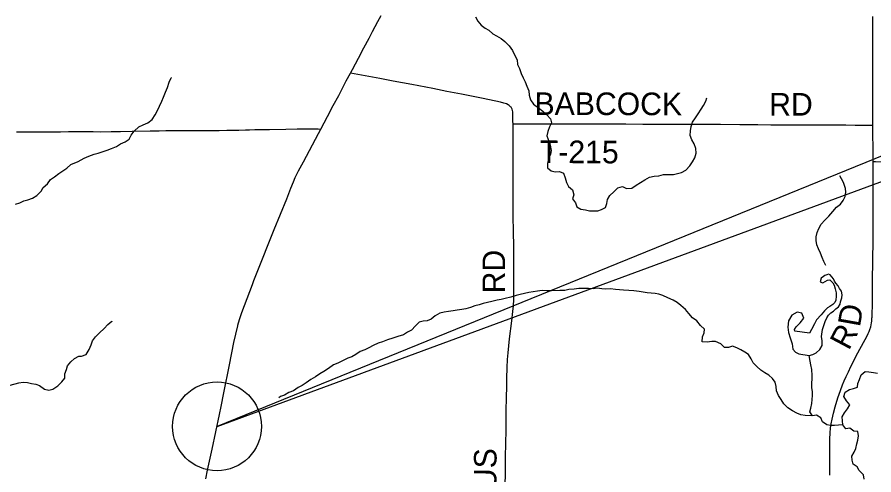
# Model space of a CAD drawing. Extents: x 0 to 34, y 0 to 22.
# Drawn here: x 15.63 to 17.787, y 16.085 to 17.236 of the extents above; entities that cross this region are included whole.
import ezdxf

# ---------------------------------------------------------------- set-up
doc = ezdxf.new("R2010")
doc.units = 0
for name, color, linetype in [('GM_X_County_Road', 7, 'Continuous'), ('GM_X_County_Road_Text', 7, 'Continuous'), ('GM_X_Minor_Lake', 7, 'Continuous'), ('GM_X_Minor_River', 7, 'Continuous'), ('GM_X_State_Route', 7, 'Continuous'), ('GM_X_Township_Road', 7, 'Continuous'), ('GM_X_Township_Road_Text', 7, 'Continuous'), ('SH_Text', 7, 'Continuous')]:
    doc.layers.add(name, color=color, linetype=linetype)

msp = doc.modelspace()

# ---------------------------------------------------------------- linework, layer by layer
at = {"layer": 'GM_X_County_Road'}
for points in [[(17.785, 16.9644), (17.7849, 16.9936), (17.7849, 17.0066), (17.7849, 17.0109), (17.7848, 17.0153), (17.7848, 17.0339), (17.7849, 17.0472), (17.7848, 17.0794), (17.7848, 17.1046), (17.7848, 17.1278), (17.7846, 17.1444), (17.785, 17.1634), (17.785, 17.1754), (17.785, 17.1878), (17.7848, 17.2189), (17.7849, 17.2294), (17.7851, 17.2381)], [(15.6289, 16.9476), (15.6413, 16.9475), (15.6692, 16.9475), (15.7053, 16.9477), (15.7394, 16.9478), (15.7593, 16.9481), (15.7829, 16.9481), (15.8214, 16.9481), (15.8401, 16.948), (15.8668, 16.9483), (15.891, 16.9487), (15.9196, 16.9491), (15.965, 16.9498), (15.988, 16.9502), (16.0047, 16.9506), (16.0121, 16.9508), (16.0237, 16.9509), (16.0334, 16.9509), (16.039, 16.9509), (16.0514, 16.9508), (16.0725, 16.9511), (16.0843, 16.9512), (16.1109, 16.9511), (16.1388, 16.9513), (16.1587, 16.9517), (16.1742, 16.9519), (16.1885, 16.9522), (16.2052, 16.9526), (16.2151, 16.9528), (16.2287, 16.9531), (16.2435, 16.9533), (16.2661, 16.9537), (16.307, 16.9546), (16.3357, 16.9555), (16.3588, 16.9554), (16.3788, 16.9554), (16.3881, 16.955), (16.395, 16.9547)], [(17.7857, 16.8731), (17.7854, 16.8924), (17.7855, 16.9048), (17.7852, 16.9165), (17.7851, 16.9315), (17.7851, 16.9514), (17.7851, 16.9588), (17.785, 16.9644)], [(17.6763, 16.0838), (17.6762, 16.0944), (17.6763, 16.108), (17.6764, 16.1328), (17.6764, 16.1433), (17.6764, 16.1538), (17.6765, 16.1633), (17.6767, 16.1746), (17.6774, 16.1905), (17.6784, 16.2022), (17.6799, 16.2131), (17.682, 16.2252), (17.6858, 16.2402), (17.69, 16.2555), (17.697, 16.2782), (17.703, 16.2971), (17.7083, 16.3109), (17.7126, 16.3212), (17.7172, 16.3318), (17.7231, 16.3441), (17.7296, 16.3577), (17.7467, 16.3915), (17.7613, 16.4181), (17.7698, 16.4332), (17.7733, 16.4403), (17.7754, 16.4452), (17.7773, 16.4504), (17.7795, 16.4574), (17.7806, 16.4623), (17.7816, 16.4674), (17.7821, 16.4711), (17.7823, 16.4741), (17.7826, 16.4767), (17.7826, 16.4792), (17.7827, 16.4816), (17.7829, 16.485), (17.7832, 16.4949), (17.7835, 16.5067), (17.7837, 16.5185), (17.7839, 16.5313), (17.7837, 16.5485), (17.7839, 16.566), (17.7843, 16.5848), (17.7848, 16.6119), (17.7851, 16.6376), (17.7854, 16.6614), (17.7857, 16.6947), (17.7857, 16.7216), (17.7858, 16.7425), (17.7859, 16.7611), (17.7857, 16.7939), (17.7859, 16.8123), (17.7859, 16.8477), (17.7857, 16.872), (17.7857, 16.8731)]]:
    msp.add_lwpolyline(points, dxfattribs=at)
at = {"layer": 'GM_X_Minor_Lake'}
msp.add_line((17.598, 16.389), (17.6242, 16.3847), dxfattribs=at)
msp.add_lwpolyline([(17.6242, 16.3847), (17.634, 16.3879), (17.6423, 16.3921), (17.6509, 16.3998), (17.6568, 16.4101), (17.6575, 16.4223), (17.6554, 16.4329), (17.6583, 16.45), (17.6616, 16.4603), (17.6649, 16.4706), (17.6689, 16.4798), (17.6734, 16.4867), (17.6786, 16.4924), (17.6858, 16.4967), (17.6914, 16.5021), (17.6982, 16.5078), (17.7023, 16.514), (17.7033, 16.5197), (17.7066, 16.5303), (17.7073, 16.5376), (17.7057, 16.5467), (17.7007, 16.5534), (17.6976, 16.5599), (17.6918, 16.567), (17.688, 16.5719), (17.6856, 16.5779), (17.6814, 16.5828), (17.6772, 16.5877), (17.673, 16.5896), (17.6685, 16.5876), (17.664, 16.586), (17.6606, 16.5837), (17.6546, 16.5795), (17.6524, 16.5703), (17.6589, 16.5678), (17.6645, 16.5712), (17.6709, 16.5747), (17.6766, 16.5756), (17.6842, 16.5681), (17.687, 16.562), (17.6901, 16.5526), (17.6928, 16.5427), (17.6926, 16.5344), (17.6919, 16.5241), (17.689, 16.5184), (17.6841, 16.5134), (17.6766, 16.508), (17.6706, 16.5045), (17.6627, 16.4972), (17.6548, 16.4876), (17.6429, 16.4745), (17.6377, 16.4646), (17.6302, 16.4508), (17.625, 16.4413), (17.5883, 16.4458), (17.5878, 16.45), (17.5915, 16.4568), (17.6017, 16.4672), (17.6114, 16.4787), (17.6063, 16.4912), (17.5938, 16.4937), (17.581, 16.4867), (17.5721, 16.4726), (17.5707, 16.4562), (17.5728, 16.4426), (17.5767, 16.4297), (17.5818, 16.4146), (17.5835, 16.4006), (17.5896, 16.393), (17.598, 16.389)], dxfattribs=at)
at = {"layer": 'GM_X_Minor_River'}
for points in [[(16.7845, 17.2373), (16.7899, 17.2264), (16.7987, 17.2162), (16.8083, 17.208), (16.8178, 17.2031), (16.8277, 17.1945), (16.8376, 17.1893), (16.8491, 17.1822), (16.8586, 17.1751), (16.8694, 17.1642), (16.8778, 17.1526), (16.8836, 17.1397), (16.8891, 17.1284), (16.8903, 17.1174), (16.8954, 17.1072), (16.8993, 17.094), (16.9047, 17.0838), (16.909, 17.0732), (16.9137, 17.0622), (16.9187, 17.0505), (16.9192, 17.0395), (16.9231, 17.0285), (16.9308, 17.0176), (16.9431, 17.0079), (16.9538, 16.9993), (16.9637, 16.9903), (16.9733, 16.9805), (16.9753, 16.9699), (16.9709, 16.9604), (16.9661, 16.9485), (16.9639, 16.9375), (16.969, 16.9243), (16.9725, 16.9144), (16.9746, 16.9008), (16.9728, 16.8913), (16.968, 16.8798), (16.9654, 16.868), (16.9656, 16.8574), (16.9751, 16.8499), (16.9846, 16.8473), (16.9956, 16.8479), (17.0062, 16.8438), (17.0105, 16.8317), (17.0133, 16.8203), (17.0187, 16.8105), (17.0287, 16.8019), (17.0318, 16.7894), (17.0289, 16.7787), (17.0359, 16.769), (17.0398, 16.7591), (17.0493, 16.7532), (17.0614, 16.751), (17.0713, 16.7492), (17.0819, 16.7486), (17.0921, 16.7491), (17.1019, 16.7519), (17.1117, 16.7573), (17.115, 16.7676), (17.1164, 16.7775), (17.1224, 16.7874), (17.1325, 16.797), (17.1426, 16.807), (17.1543, 16.8098), (17.1646, 16.805), (17.1779, 16.8056), (17.1888, 16.8133), (17.2106, 16.8272), (17.2222, 16.8334), (17.2343, 16.8362), (17.2461, 16.8371), (17.2578, 16.8407), (17.2714, 16.8404), (17.2828, 16.8406), (17.3032, 16.8454), (17.3137, 16.8516), (17.3242, 16.8623), (17.3309, 16.8723), (17.3365, 16.8822), (17.3401, 16.894), (17.3389, 16.9054)], [(15.7837, 16.8732), (15.7992, 16.8814), (15.8112, 16.8868), (15.824, 16.8912), (15.8346, 16.8936), (15.8471, 16.8983), (15.8573, 16.9014), (15.8678, 16.9057), (15.8803, 16.9108), (15.8908, 16.9178), (15.9025, 16.9224), (15.9126, 16.929), (15.9174, 16.9393), (15.9253, 16.9493), (15.9369, 16.9604), (15.9478, 16.9651), (15.9595, 16.9702), (15.97, 16.9787), (15.9782, 16.9902), (15.9834, 17.0012), (15.9886, 17.0119), (15.9945, 17.0249), (15.9989, 17.0348), (16.0037, 17.0471), (16.0089, 17.0589), (16.0133, 17.0726), (16.0185, 17.0837), (16.0192, 17.0841)], [(17.3389, 16.9054), (17.3349, 16.9171), (17.3291, 16.9273), (17.3252, 16.9383), (17.3255, 16.9504), (17.3276, 16.9607), (17.3309, 16.9722), (17.338, 16.9829), (17.3447, 16.9932), (17.3529, 17.0043), (17.3581, 17.0142), (17.364, 17.0249), (17.3666, 17.0329)], [(15.6264, 16.7657), (15.6373, 16.7689), (15.6475, 16.7739), (15.6573, 16.7766), (15.6694, 16.7809), (15.6803, 16.7874), (15.6905, 16.7981), (15.6961, 16.8076), (15.707, 16.8172), (15.7145, 16.8279), (15.7246, 16.8348), (15.7352, 16.8424), (15.7453, 16.8497), (15.7551, 16.8559), (15.7653, 16.8658), (15.7837, 16.8732)], [(17.666, 16.6111), (17.6613, 16.6217), (17.6574, 16.6319), (17.6527, 16.6421), (17.6481, 16.6535), (17.6434, 16.6637), (17.6418, 16.6743), (17.6424, 16.6838), (17.6442, 16.6944), (17.6486, 16.7047), (17.6546, 16.7154), (17.6639, 16.725), (17.674, 16.7358), (17.6841, 16.7469), (17.6935, 16.758), (17.7032, 16.7654), (17.71, 16.7753), (17.7152, 16.7849), (17.7165, 16.7955), (17.7161, 16.8054), (17.7106, 16.8198), (17.7056, 16.8296), (17.7013, 16.8367)], [(17.7094, 16.211), (17.6985, 16.2098), (17.6879, 16.2085), (17.678, 16.2091), (17.6685, 16.2109), (17.6578, 16.218), (17.6536, 16.2282), (17.6429, 16.2353), (17.6327, 16.2333), (17.6145, 16.2338), (17.6035, 16.236), (17.5932, 16.2397), (17.5822, 16.2456), (17.5703, 16.2531), (17.5604, 16.2636), (17.5538, 16.2741), (17.5473, 16.2843), (17.5422, 16.2964), (17.5417, 16.3067), (17.5386, 16.3176), (17.532, 16.3274), (17.5225, 16.3353), (17.5125, 16.3412), (17.503, 16.3483), (17.493, 16.3573), (17.4831, 16.3667), (17.4781, 16.3765), (17.4719, 16.3871), (17.4623, 16.3931), (17.4524, 16.399), (17.4421, 16.4046), (17.4311, 16.4083), (17.4213, 16.4051), (17.4115, 16.4054), (17.4019, 16.414), (17.3889, 16.4199), (17.3795, 16.4206), (17.3674, 16.4182), (17.3549, 16.4195), (17.3555, 16.4317), (17.3603, 16.442), (17.3609, 16.4515), (17.351, 16.4605), (17.3414, 16.4718), (17.3307, 16.48), (17.3211, 16.4905), (17.3131, 16.5007), (17.3016, 16.5104), (17.2917, 16.5183), (17.2821, 16.5242), (17.2684, 16.5298), (17.2558, 16.5361), (17.2463, 16.5394), (17.2369, 16.5408), (17.2266, 16.5422), (17.2164, 16.5428), (17.1967, 16.5456), (17.1826, 16.5474), (17.1701, 16.5484), (17.1569, 16.5494), (17.147, 16.5504), (17.1371, 16.5506), (17.1239, 16.5524), (17.1117, 16.5522), (17.1023, 16.5529), (17.0905, 16.5543), (17.0807, 16.5523), (17.0689, 16.5533), (17.0576, 16.5539), (17.0447, 16.5534), (17.0326, 16.5521), (17.0193, 16.5512), (17.0095, 16.5488), (16.9967, 16.5482), (16.9754, 16.548), (16.9641, 16.5475), (16.9523, 16.5481), (16.9402, 16.5468), (16.9293, 16.5448), (16.9183, 16.5435), (16.9077, 16.5411), (16.8968, 16.5387), (16.8866, 16.5363), (16.873, 16.532), (16.859, 16.5284), (16.8492, 16.5256), (16.8386, 16.524), (16.8254, 16.5208), (16.8148, 16.5184), (16.8035, 16.516), (16.7933, 16.5128), (16.7823, 16.51), (16.7714, 16.5061), (16.7601, 16.5026), (16.7499, 16.5006), (16.7381, 16.4993), (16.7283, 16.4976), (16.7166, 16.4956), (16.7053, 16.494), (16.6943, 16.4912), (16.6826, 16.485)], [(16.6826, 16.485), (16.6725, 16.4765), (16.6623, 16.4726), (16.6525, 16.4713), (16.6423, 16.4689), (16.6329, 16.4593), (16.6236, 16.449), (16.6134, 16.4435), (16.6029, 16.4373), (16.5885, 16.433), (16.5761, 16.429), (16.5629, 16.4243), (16.5504, 16.4192), (16.5395, 16.4157), (16.5267, 16.4098), (16.5154, 16.4044), (16.5056, 16.3994), (16.4943, 16.395), (16.483, 16.3877), (16.4728, 16.3815), (16.463, 16.3783), (16.4498, 16.3717), (16.4378, 16.3659), (16.4268, 16.3616), (16.4144, 16.3527), (16.4024, 16.345), (16.3926, 16.3388), (16.3817, 16.3311), (16.3701, 16.3245), (16.3584, 16.316), (16.3479, 16.3094), (16.3377, 16.3044), (16.3261, 16.2962), (16.3147, 16.2919), (16.3038, 16.2854), (16.2933, 16.2818), (16.2891, 16.2787)], [(15.7922, 16.3831), (15.8043, 16.3874), (15.8121, 16.4), (15.8165, 16.4122), (15.8198, 16.4221), (15.8276, 16.4321), (15.8374, 16.4421), (15.8494, 16.4525), (15.8587, 16.4632), (15.8685, 16.4717), (15.8685, 16.4709)], [(15.5909, 16.3046), (15.6344, 16.3163), (15.6453, 16.3179), (15.6563, 16.3169), (15.6666, 16.3147), (15.6772, 16.3129), (15.6867, 16.3095), (15.6996, 16.3005), (15.7102, 16.298), (15.7204, 16.3003), (15.7328, 16.3084), (15.743, 16.3187), (15.7505, 16.3282), (15.7504, 16.3392), (15.7545, 16.3495), (15.757, 16.3594), (15.7653, 16.3689), (15.7751, 16.3777), (15.786, 16.3831), (15.7922, 16.3831)], [(17.6327, 16.2333), (17.6265, 16.2431), (17.6287, 16.2526), (17.6308, 16.2644), (17.6322, 16.2743), (17.6325, 16.2842), (17.6328, 16.2937), (17.6315, 16.3043), (17.6314, 16.3161), (17.632, 16.3256), (17.6319, 16.335), (17.631, 16.3495), (17.629, 16.3612), (17.627, 16.3711), (17.6242, 16.3847)], [(17.7628, 16.0738), (17.7612, 16.0848), (17.7501, 16.0953), (17.7455, 16.1051), (17.7355, 16.1115), (17.7324, 16.1217), (17.7315, 16.1319), (17.7375, 16.1415), (17.7419, 16.1514), (17.7444, 16.1628), (17.7466, 16.1724), (17.7487, 16.183), (17.7471, 16.194), (17.7373, 16.1946), (17.7269, 16.2021), (17.7171, 16.2009), (17.7094, 16.211), (17.7082, 16.2209), (17.7077, 16.2304), (17.7136, 16.2407), (17.7207, 16.2507), (17.7267, 16.261), (17.7186, 16.2711), (17.7113, 16.2821), (17.7153, 16.2927), (17.7259, 16.2997), (17.7357, 16.3021), (17.7459, 16.3052), (17.7473, 16.3148), (17.751, 16.3247), (17.7554, 16.3361), (17.7651, 16.345), (17.7746, 16.3436), (17.7864, 16.3426), (17.7966, 16.3408)]]:
    msp.add_lwpolyline(points, dxfattribs=at)
at = {"layer": 'GM_X_State_Route'}
msp.add_lwpolyline([(16.1051, 16.0747), (16.1099, 16.0965), (16.1214, 16.1494), (16.1398, 16.2363), (16.144, 16.257), (16.151, 16.2911), (16.1651, 16.3618), (16.1763, 16.4178), (16.1857, 16.4598), (16.186, 16.4613), (16.1901, 16.4756), (16.1923, 16.4828), (16.1961, 16.4933), (16.2226, 16.5637), (16.2264, 16.5735), (16.2331, 16.5903), (16.2778, 16.7023), (16.2932, 16.7402), (16.309, 16.7794), (16.3194, 16.806), (16.3258, 16.8215), (16.3306, 16.8329), (16.3328, 16.838), (16.3388, 16.8496), (16.3427, 16.8567), (16.3469, 16.8643), (16.351, 16.872), (16.3665, 16.901), (16.389, 16.9432), (16.395, 16.9547), (16.4116, 16.9861), (16.4262, 17.0135), (16.44, 17.0393), (16.4591, 17.0755), (16.4697, 17.0952), (16.4744, 17.104), (16.4894, 17.1326), (16.5033, 17.1589), (16.5165, 17.1836), (16.5252, 17.2001), (16.5386, 17.2253), (16.5469, 17.2406)], dxfattribs=at)
at = {"layer": 'GM_X_Township_Road'}
for points in [[(16.8788, 16.9675), (16.8786, 16.9736), (16.8783, 16.9848), (16.8783, 16.9879), (16.8781, 16.998), (16.8774, 17.0012), (16.8763, 17.0048), (16.8738, 17.0093), (16.8726, 17.0108), (16.8693, 17.0139), (16.8667, 17.0157), (16.8621, 17.018), (16.8561, 17.02), (16.8476, 17.0221), (16.8037, 17.0313), (16.7495, 17.0424), (16.7123, 17.0494), (16.6769, 17.0566), (16.6244, 17.0666), (16.5767, 17.0753), (16.5432, 17.0816), (16.4974, 17.0901), (16.4791, 17.0935), (16.4697, 17.0952)], [(16.8591, 16.0578), (16.8595, 16.0889), (16.8603, 16.1299), (16.8614, 16.197), (16.8618, 16.2455), (16.8624, 16.2797), (16.8629, 16.307), (16.863, 16.3269), (16.8638, 16.3548), (16.8648, 16.3753), (16.8662, 16.392), (16.87, 16.4272), (16.8756, 16.4722), (16.8785, 16.4957), (16.8799, 16.5099), (16.8808, 16.5255), (16.881, 16.5423), (16.8811, 16.5715), (16.8812, 16.592), (16.8811, 16.6231), (16.8805, 16.6604), (16.8799, 16.6964), (16.8794, 16.7362), (16.8795, 16.7648), (16.8794, 16.8008), (16.8795, 16.8418), (16.8795, 16.8754), (16.8796, 16.8891), (16.8792, 16.9177), (16.8791, 16.9431), (16.879, 16.9618), (16.8788, 16.9675)], [(16.8788, 16.9675), (16.8839, 16.9676), (16.8942, 16.9677), (16.934, 16.9679), (16.967, 16.9677), (17.0071, 16.9677), (17.0413, 16.9674), (17.078, 16.9676), (17.1283, 16.9678), (17.1631, 16.9677), (17.206, 16.9673), (17.2252, 16.967), (17.2495, 16.9666), (17.2719, 16.9668), (17.3153, 16.9666), (17.3359, 16.9667), (17.3483, 16.9668), (17.4014, 16.9666), (17.4501, 16.9663), (17.4951, 16.966), (17.5278, 16.9655), (17.5638, 16.9655), (17.5992, 16.9652), (17.652, 16.9651), (17.6646, 16.965), (17.6911, 16.965), (17.7166, 16.9649), (17.7401, 16.9648), (17.7801, 16.9645), (17.785, 16.9644)], [(17.7857, 16.8731), (17.7916, 16.873), (17.8621, 16.8722), (17.9719, 16.8711), (17.9793, 16.8705), (17.9864, 16.8689), (17.9898, 16.8677), (17.9937, 16.866), (17.9996, 16.8626), (18.0046, 16.8591), (18.0106, 16.8548), (18.0138, 16.8522)]]:
    msp.add_lwpolyline(points, dxfattribs=at)
at = {"layer": 'SH_Text'}
msp.add_lwpolyline([(20.5238, 17.992), (16.1336, 16.2067), (20.98, 17.992), (20.5238, 17.992)], dxfattribs=at)
msp.add_circle((16.1336, 16.2067), 0.1118, dxfattribs=at)

# ---------------------------------------------------------------- texts
at = {"layer": 'GM_X_County_Road_Text'}
for s, rotation, p in [('D', 79.8842, (17.752, 16.4549)), ('R', 62.1013, (17.7241, 16.3958))]:
    msp.add_text(s, height=0.0568, rotation=rotation, dxfattribs=at).set_placement(p)
at = {"layer": 'GM_X_Township_Road_Text'}
for s, rotation, p in [('BABCOCK', 359.8583, (16.9329, 16.9902)), ('RD', 0, (17.5238, 16.9885)), ('T-215', 359.7181, (16.9463, 16.8692)), ('RD', 90, (16.8589, 16.5412)), ('NICODEMUS', 89.5401, (16.8339, 15.6872))]:
    msp.add_text(s, height=0.05682, rotation=rotation, dxfattribs=at).set_placement(p)

doc.saveas('drawing.dxf')
